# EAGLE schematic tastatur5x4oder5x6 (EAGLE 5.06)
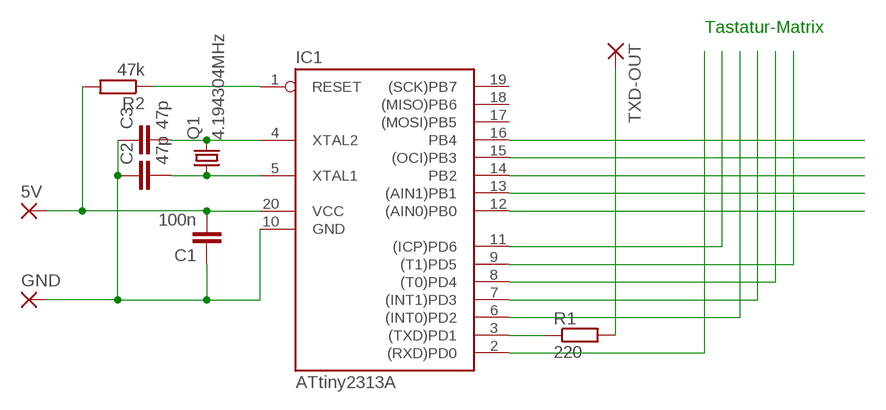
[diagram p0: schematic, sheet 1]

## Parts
5V  1,6/0,8  [1,6/0,8]
C1  100n  C2.5/2  [C2.5-2]
C2  47p  C2.5/2  [C2.5-2]
C3  47p  C2.5/2  [C2.5-2]
GND  1,6/0,8  [1,6/0,8]
IC1  ATtiny2313A  AT90S2313P  [DIL20]
Q1  4.194304MHz  CRYTALHC49U-V  [HC49U-V]
R1  220  R-EU_0204/7  [0204/7]
R2  47k  R-EU_0204/7  [0204/7]
TXD-OUT  1,6/0,8  [1,6/0,8]

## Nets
GND [mitteldick]: C1.1 C2.1 C3.1 GND.1(P) IC1.10(GND)
N$1: IC1.12((AIN0)PB0)
N$2: IC1.13((AIN1)PB1)
N$3: IC1.14(PB2)
N$4: IC1.15((OCI)PB3)
N$5: IC1.16(PB4)
N$6: IC1.2((RXD)PD0)
N$7: IC1.11((ICP)PD6)
N$8: IC1.6((INT0)PD2)
N$9: IC1.7((INT1)PD3)
N$10: IC1.8((T0)PD4)
N$11: IC1.9((T1)PD5)
N$12: IC1.3((TXD)PD1) R1.1
N$13: R1.2 TXD-OUT.1(P)
N$152: C3.2 IC1.4(XTAL2) Q1.2
N$153: C2.2 IC1.5(XTAL1) Q1.1
N$156: IC1.1(RESET) R2.1
VCC [mitteldick]: 5V.1(P) C1.2 IC1.20(VCC) R2.2
Unconnected: IC1.17((MOSI)PB5) IC1.18((MISO)PB6) IC1.19((SCK)PB7)

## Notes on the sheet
- Tastatur-Matrix

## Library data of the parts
5V GND TXD-OUT = wirepad:1,6/0,8: THROUGH-HOLE PAD
C1-C3 = capacitor-wima:C: CAPACITOR
IC1 = atmel:AT90S2313: MICROCONTROLLER 2 Kbytes FLASH 128 bytes SRAM 128 bytes EEPROM UART
Q1 = crystal:CRYTAL: CRYSTAL
R1 R2 = rcl:R-EU_: RESISTOR, European symbol

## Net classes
1 dick: width 1.016 mm, clearance 0.61 mm
2 mitteldick: width 0.762 mm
